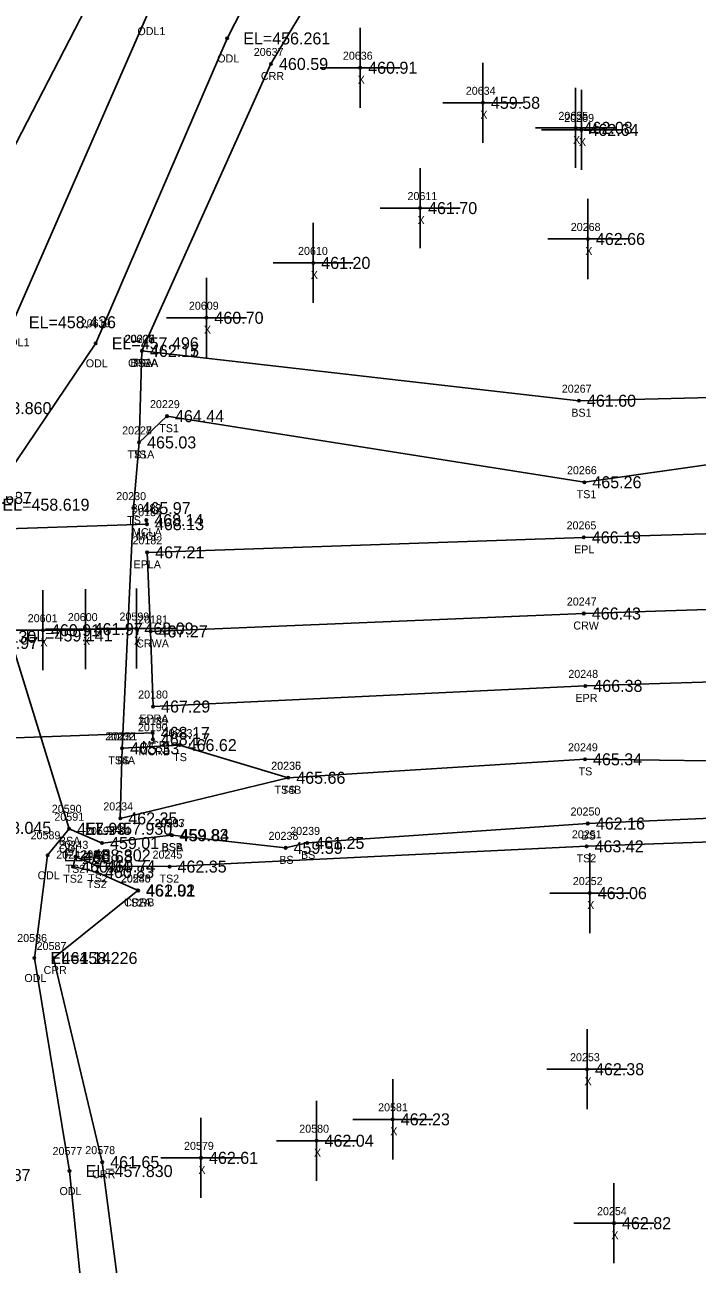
# Model space of a CAD drawing. Extents: x 1785066 to 1786589, y 770293 to 771312.
# Drawn here: x 1785809.3 to 1785893.3, y 770775.9 to 770930.8 of the extents above; entities that cross this region are included whole.
import ezdxf

# ---------------------------------------------------------------- set-up
doc = ezdxf.new("R2010")
doc.units = 0
for name, color, linetype in [('BR_500YR_SCOUR', 7, 'Continuous'), ('RD_DTM_BkLn1', 7, 'Continuous'), ('RD_DTM_BkLn2', 7, 'Continuous'), ('RD_DTM_BkLn_txCode', 7, 'Continuous'), ('RD_EX_Conc_txCode', 7, 'Continuous'), ('RD_EX_H2O', 7, 'Continuous'), ('RD_EX_H2O_txCode', 7, 'Continuous'), ('RD_EX_Misc', 7, 'Continuous'), ('RD_EX_Misc_txCode', 7, 'Continuous'), ('RD_EX_Road', 7, 'Continuous'), ('RD_EX_Road_txCode', 7, 'Continuous'), ('RD_EX_TX_Conc_ELEV', 7, 'Continuous'), ('RD_EX_TX_H2O_ELEV', 7, 'Continuous'), ('RD_EX_TX_Misc_ELEV', 7, 'Continuous'), ('RD_EX_TX_Road_ELEV', 7, 'Continuous'), ('RD_HC_Survey_ELEV', 7, 'Continuous'), ('RD_HC_Survey_txCode', 7, 'Continuous'), ('RD_SMD_Locator', 7, 'Continuous')]:
    doc.layers.add(name, color=color, linetype=linetype)

msp = doc.modelspace()

# ---------------------------------------------------------------- linework, layer by layer
at = {"layer": 'BR_500YR_SCOUR'}
for points in [[(1785824.45, 770868.88), (1785824.54, 770868.38), (1785779.78, 770866.9), (1785779.66, 770867.5)], [(1785780.7, 770840.08), (1785780.59, 770840.7), (1785825.26, 770842.31), (1785825.28, 770841.51)]]:
    msp.add_lwpolyline(points, dxfattribs=at)
for centre in [(1785824.45, 770868.88), (1785824.54, 770868.38), (1785825.26, 770842.31), (1785825.28, 770841.51)]:
    msp.add_circle(centre, 0.15, dxfattribs=at)
at = {"layer": 'RD_DTM_BkLn1'}
msp.add_lwpolyline([(1785825, 770854.98), (1785879.1, 770857.22), (1785979.05, 770860.47), (1786078.95, 770863.87), (1786178.85, 770867.23), (1786278.74, 770870.52), (1786378.69, 770873.93), (1786478.55, 770877.83), (1786578.48, 770880.72)], dxfattribs=at)
at = {"layer": 'RD_DTM_BkLn2'}
for points in [[(1785823.92, 770890.03), (1785878.49, 770883.8), (1785927.98, 770885.02), (1785976.75, 770881.71), (1786078.01, 770885.31), (1786179.02, 770889.42), (1786277.82, 770892.61), (1786356.85, 770898.28)], [(1785823.56, 770878.59), (1785827.04, 770881.87), (1785879.17, 770873.62), (1785928.77, 770880.68), (1785976.07, 770878.36), (1786078.31, 770882.72), (1786179.21, 770888.23), (1786278, 770891.06), (1786358.22, 770894.11)], [(1785823.92, 770890.03), (1785823.56, 770878.59), (1785822.86, 770870.38), (1785821.44, 770840.38), (1785828.62, 770840.78), (1785842.19, 770836.7), (1785879.25, 770839.01), (1785978.35, 770837.69), (1786078.6, 770842.58), (1786178.83, 770845.52), (1786229.23, 770850.73), (1786230.88, 770847.03), (1786230.86, 770843.81)], [(1785827.67, 770829.52), (1785841.85, 770827.95), (1785844.56, 770828.57), (1785879.6, 770830.99), (1785978.6, 770835.28), (1786078.94, 770840.43), (1786179.05, 770843.41), (1786228.83, 770846.64)], [(1785823.45, 770822.61), (1785818.3, 770824.93), (1785815.32, 770825.6), (1785815.62, 770826.83), (1785818.45, 770825.65), (1785827.36, 770825.61), (1785879.44, 770828.14), (1785979.38, 770831.62), (1786079.14, 770836.17), (1786182.02, 770840.89), (1786230.86, 770843.81)], [(1785821.44, 770840.38), (1785821.21, 770831.63), (1785842.19, 770836.7)], [(1785814.82, 770830.33), (1785818.93, 770828.55), (1785827.6, 770829.55)]]:
    msp.add_lwpolyline(points, dxfattribs=at)
at = {"layer": 'RD_EX_H2O'}
for points in [[(1785796.94, 770894.21), (1785817.52, 770934.08), (1785841.28, 770978.27), (1785905.84, 771069.13), (1785934.06, 771107.4), (1785932.74, 771138.87), (1785957.1, 771183.16), (1785993.97, 771208.54), (1785990.48, 771236.16), (1786004.55, 771296.27)], [(1785809.1, 770721.92), (1785797.13, 770787.08), (1785799.71, 770830.45), (1785797.84, 770854.32), (1785797.31, 770871.66), (1785799.74, 770882.87), (1785807.79, 770893.6), (1785824.76, 770932.46), (1785830, 770936.66), (1785845.12, 770978.01), (1785907.84, 771068.37), (1785939.25, 771107.77), (1785943.33, 771137.21), (1785960.57, 771178.58), (1785995.85, 771206.75), (1786007.06, 771230.75), (1786010.67, 771288.67)], [(1785820.66, 770730.64), (1785814.87, 770787.58), (1785810.48, 770814.19), (1785812.13, 770827.02), (1785814.82, 770830.33), (1785807.38, 770854.48), (1785804.49, 770870.81), (1785818.14, 770890.97), (1785834.56, 770929.05), (1785857.87, 770974.7), (1785917.08, 771062.46), (1785943.86, 771096.04), (1785952.84, 771134.11), (1785966.16, 771175.54), (1786004.33, 771202.23), (1786012.95, 771230.11), (1786017.56, 771287.45)], [(1785823.91, 770890.02), (1785840.03, 770925.86), (1785869.79, 770975.48), (1785920.39, 771060.62), (1785947.12, 771092.26), (1785958.51, 771131.14), (1785974.06, 771169.93), (1786009.64, 771197.71), (1786027.99, 771233.04), (1786021.73, 771286.51)], [(1785996.34, 770328.69), (1785988.37, 770343.77), (1785978.71, 770369.85), (1785965.55, 770429.48), (1785948.02, 770485.76), (1785915.42, 770547.17), (1785885.85, 770601.99), (1785867.88, 770639.76), (1785836.38, 770688.5), (1785826.2, 770733.3), (1785818.95, 770788.69), (1785812.88, 770814.19), (1785823.4, 770822.64)]]:
    msp.add_lwpolyline(points, dxfattribs=at)
at = {"layer": 'RD_EX_Misc'}
for p, q in [((1785851.17, 770920.39), (1785851.17, 770930.39)), ((1785846.17, 770925.39), (1785856.17, 770925.39)), ((1785866.5, 770916.01), (1785866.5, 770926.01)), ((1785878.07, 770912.88), (1785878.07, 770922.88)), ((1785878.8, 770912.62), (1785878.8, 770922.62)), ((1785861.5, 770921.01), (1785871.5, 770921.01)), ((1785873.07, 770917.88), (1785883.07, 770917.88)), ((1785873.8, 770917.62), (1785883.8, 770917.62)), ((1785858.65, 770902.86), (1785858.65, 770912.86)), ((1785853.65, 770907.86), (1785863.65, 770907.86)), ((1785879.61, 770899), (1785879.61, 770909)), ((1785845.31, 770896.01), (1785845.31, 770906.01)), ((1785874.61, 770904), (1785884.61, 770904)), ((1785840.31, 770901.01), (1785850.31, 770901.01)), ((1785831.97, 770889.16), (1785831.97, 770899.16)), ((1785826.97, 770894.16), (1785836.97, 770894.16)), ((1785811.55, 770850.13), (1785811.55, 770860.13)), ((1785816.88, 770850.27), (1785816.88, 770860.27)), ((1785823.23, 770850.34), (1785823.23, 770860.34)), ((1785806.55, 770855.13), (1785816.55, 770855.13)), ((1785811.88, 770855.27), (1785821.88, 770855.27)), ((1785818.23, 770855.34), (1785828.23, 770855.34)), ((1785879.84, 770817.3), (1785879.84, 770827.3)), ((1785874.84, 770822.3), (1785884.84, 770822.3)), ((1785879.5, 770795.3), (1785879.5, 770805.3)), ((1785874.5, 770800.3), (1785884.5, 770800.3)), ((1785855.24, 770789.04), (1785855.24, 770799.04)), ((1785845.72, 770786.37), (1785845.72, 770796.37)), ((1785831.29, 770784.23), (1785831.29, 770794.23)), ((1785850.24, 770794.04), (1785860.24, 770794.04)), ((1785840.72, 770791.37), (1785850.72, 770791.37)), ((1785826.29, 770789.23), (1785836.29, 770789.23)), ((1785882.87, 770776.07), (1785882.87, 770786.07)), ((1785877.87, 770781.07), (1785887.87, 770781.07))]:
    msp.add_line(p, q, dxfattribs=at)
at = {"layer": 'RD_EX_Road'}
for points in [[(1785824.57, 770864.86), (1785879.1, 770866.73), (1785977.08, 770869.67), (1786078.78, 770873.52), (1786179.09, 770876.83), (1786278.08, 770880.28), (1786358.72, 770883.31), (1786381.38, 770883.94), (1786478.25, 770886.75), (1786578.04, 770889.63)], [(1785825.31, 770845.6), (1785879.29, 770848.18), (1785979.17, 770851.29), (1786079.29, 770854.66), (1786178.79, 770858.1), (1786233.56, 770860.16), (1786246.2, 770860.52), (1786278.61, 770861.3), (1786379.15, 770864.94), (1786479.01, 770868.57), (1786578.78, 770871.53)], [(1785825.31, 770845.6), (1785825, 770854.98), (1785824.57, 770864.86)]]:
    msp.add_lwpolyline(points, dxfattribs=at)
at = {"layer": 'RD_SMD_Locator'}
for centre in [(1785834.56, 770929.05), (1785840.03, 770925.86), (1785851.17, 770925.39), (1785866.5, 770921.01), (1785878.07, 770917.88), (1785878.8, 770917.62), (1785858.65, 770907.86), (1785879.61, 770904), (1785845.31, 770901.01), (1785831.97, 770894.16), (1785818.14, 770890.97), (1785823.91, 770890.02), (1785823.92, 770890.03), (1785823.92, 770890.03), (1785878.49, 770883.8), (1785827.04, 770881.87), (1785823.56, 770878.59), (1785823.56, 770878.59), (1785879.17, 770873.62), (1785822.86, 770870.38), (1785879.1, 770866.73), (1785824.57, 770864.86), (1785879.1, 770857.22), (1785811.55, 770855.13), (1785816.88, 770855.27), (1785823.23, 770855.34), (1785825, 770854.98), (1785879.29, 770848.18), (1785825.31, 770845.6), (1785821.44, 770840.38), (1785821.44, 770840.38), (1785828.62, 770840.78), (1785879.25, 770839.01), (1785842.19, 770836.7), (1785842.19, 770836.7), (1785814.82, 770830.33), (1785814.82, 770830.33), (1785821.21, 770831.63), (1785879.6, 770830.99), (1785827.6, 770829.55), (1785827.67, 770829.52), (1785844.56, 770828.57), (1785812.13, 770827.02), (1785818.93, 770828.55), (1785841.85, 770827.95), (1785879.44, 770828.14), (1785815.32, 770825.6), (1785815.62, 770826.83), (1785818.45, 770825.65), (1785827.36, 770825.61), (1785818.3, 770824.93), (1785823.4, 770822.64), (1785823.45, 770822.61), (1785879.84, 770822.3), (1785810.48, 770814.19), (1785812.88, 770814.19), (1785879.5, 770800.3), (1785855.24, 770794.04), (1785845.72, 770791.37), (1785818.95, 770788.69), (1785831.29, 770789.23), (1785814.87, 770787.58), (1785882.87, 770781.07)]:
    msp.add_circle(centre, 0.15, dxfattribs=at)

# ---------------------------------------------------------------- texts
at = {"layer": 'RD_DTM_BkLn_txCode'}
for s, p in [('20226', (1785821.78, 770891.03)), ('20225', (1785821.8, 770891.03)), ('BS1A', (1785822.49, 770888.03)), ('TSA', (1785822.64, 770888.03)), ('20267', (1785876.35, 770884.8)), ('20229', (1785824.92, 770882.87)), ('BS1', (1785877.54, 770881.8)), ('20227', (1785821.44, 770879.59)), ('20228', (1785821.44, 770879.59)), ('TS1', (1785826.08, 770879.87)), ('TS1A', (1785822.11, 770876.59)), ('TS', (1785822.77, 770876.59)), ('20266', (1785877, 770874.62)), ('20230', (1785820.71, 770871.38)), ('TS1', (1785878.21, 770871.62)), ('TS', (1785822.07, 770868.38)), ('20233', (1785826.5, 770841.78)), ('20232', (1785819.32, 770841.38)), ('20231', (1785819.61, 770841.38)), ('TS', (1785827.82, 770838.78)), ('20249', (1785877.13, 770840.01)), ('TS4A', (1785819.71, 770838.38)), ('TS', (1785820.64, 770838.38)), ('20236', (1785840.05, 770837.7)), ('20235', (1785840.07, 770837.7)), ('TS', (1785878.45, 770837.01)), ('TS4B', (1785840.47, 770834.7)), ('TS', (1785841.39, 770834.7)), ('20234', (1785819.09, 770832.63)), ('20591', (1785812.98, 770831.33)), ('20250', (1785877.45, 770831.99)), ('20592', (1785816.81, 770829.55)), ('TS4', (1785819.97, 770829.63)), ('20593', (1785825.49, 770830.55)), ('20237', (1785825.55, 770830.52)), ('20239', (1785842.44, 770829.57)), ('20243', (1785813.5, 770827.83)), ('BSA', (1785813.55, 770828.33)), ('20238', (1785839.73, 770828.95)), ('20251', (1785877.61, 770829.14)), ('BS', (1785878.82, 770828.99)), ('20242', (1785813.21, 770826.6)), ('20244', (1785816.33, 770826.65)), ('BS', (1785818.15, 770826.55)), ('20245', (1785825.24, 770826.61)), ('BSB', (1785826.35, 770827.55)), ('BSA', (1785826.4, 770827.52)), ('BS', (1785843.78, 770826.57)), ('TS2', (1785878.2, 770826.14)), ('TS2', (1785814.38, 770824.83)), ('20241', (1785816.46, 770825.93)), ('BS', (1785841.07, 770825.95)), ('TS2', (1785814.08, 770823.6)), ('TS2', (1785817.2, 770823.65)), ('20240', (1785821.29, 770823.61)), ('TS2', (1785826.11, 770823.61)), ('TS2', (1785817.05, 770822.93)), ('TS2A', (1785821.72, 770820.61))]:
    msp.add_text(s, height=1, dxfattribs=at).set_placement(p)
at = {"layer": 'RD_EX_Conc_txCode'}
for s, p in [('20183', (1785822.62, 770869.88)), ('20184', (1785822.7, 770869.38)), ('MCLA', (1785822.67, 770866.88)), ('MCL', (1785823.24, 770866.38)), ('20189', (1785823.43, 770843.31)), ('20190', (1785823.41, 770842.51)), ('MCR', (1785823.95, 770840.31)), ('MCRB', (1785823.5, 770839.51))]:
    msp.add_text(s, height=1, dxfattribs=at).set_placement(p)
at = {"layer": 'RD_EX_H2O_txCode'}
for s, p in [('ODL1', (1785823.35, 770929.46)), ('20637', (1785837.88, 770926.86)), ('ODL', (1785833.32, 770926.05)), ('CRR', (1785838.77, 770923.86)), ('20619', (1785816.28, 770892.97)), ('ODL1', (1785806.38, 770890.6)), ('20608', (1785821.73, 770891.02)), ('ODL', (1785816.9, 770887.97)), ('CRRA', (1785822.17, 770888.02)), ('20590', (1785812.66, 770832.33)), ('20589', (1785810.01, 770829.02)), ('ODL', (1785813.57, 770827.33)), ('ODL', (1785810.89, 770824.02)), ('20588', (1785821.28, 770823.64)), ('CRRB', (1785821.68, 770820.64)), ('20586', (1785808.34, 770816.19)), ('20587', (1785810.76, 770815.19)), ('ODL', (1785809.23, 770811.19)), ('CRR', (1785811.63, 770812.19)), ('20577', (1785812.75, 770789.58)), ('20578', (1785816.84, 770789.69)), ('CRR', (1785817.7, 770786.69)), ('ODL', (1785813.62, 770784.58))]:
    msp.add_text(s, height=1, dxfattribs=at).set_placement(p)
at = {"layer": 'RD_EX_Misc_txCode'}
for s, p in [('20636', (1785849.01, 770926.39)), ('X', (1785850.86, 770923.39)), ('20634', (1785864.36, 770922.01)), ('X', (1785866.18, 770919.01)), ('20635', (1785875.93, 770918.88)), ('20269', (1785876.66, 770918.62)), ('X', (1785877.76, 770915.88)), ('X', (1785878.49, 770915.62)), ('20611', (1785857.08, 770908.86)), ('X', (1785858.34, 770905.86)), ('20268', (1785877.47, 770905)), ('20610', (1785843.41, 770902.01)), ('X', (1785879.29, 770902)), ('X', (1785845, 770899.01)), ('20609', (1785829.78, 770895.16)), ('X', (1785831.65, 770892.16)), ('20601', (1785809.65, 770856.13)), ('20600', (1785814.66, 770856.27)), ('20599', (1785821.11, 770856.34)), ('X', (1785811.23, 770853.13)), ('X', (1785816.57, 770853.27)), ('X', (1785822.92, 770853.34)), ('20252', (1785877.73, 770823.3)), ('X', (1785879.53, 770820.3)), ('20253', (1785877.38, 770801.3)), ('X', (1785879.19, 770798.3)), ('20581', (1785853.41, 770795.04)), ('20580', (1785843.56, 770792.37)), ('X', (1785854.93, 770792.04)), ('20579', (1785829.17, 770790.23)), ('X', (1785845.4, 770789.37)), ('X', (1785830.97, 770787.23)), ('20254', (1785880.75, 770782.07)), ('X', (1785882.55, 770779.07))]:
    msp.add_text(s, height=1, dxfattribs=at).set_placement(p)
at = {"layer": 'RD_EX_Road_txCode'}
for s, p in [('20265', (1785876.95, 770867.73)), ('20182', (1785822.73, 770865.86)), ('EPL', (1785877.89, 770864.73)), ('EPLA', (1785822.87, 770862.86)), ('20248', (1785877.17, 770849.18)), ('20180', (1785823.44, 770846.6)), ('EPR', (1785878.06, 770846.18)), ('EPRA', (1785823.59, 770843.6))]:
    msp.add_text(s, height=1, dxfattribs=at).set_placement(p)
at = {"layer": 'RD_EX_TX_Conc_ELEV'}
for s, p in [('468.14', (1785825.45, 770868.13)), ('468.13', (1785825.54, 770867.63)), ('468.17', (1785826.26, 770841.56)), ('468.17', (1785826.28, 770840.76))]:
    msp.add_text(s, height=1.5, dxfattribs=at).set_placement(p)
at = {"layer": 'RD_EX_TX_H2O_ELEV'}
for s, p in [('EL=456.261', (1785836.56, 770928.3)), ('460.59', (1785841.03, 770925.11)), ('EL=458.436', (1785809.79, 770892.85)), ('EL=457.496', (1785820.14, 770890.22)), ('462.15', (1785824.91, 770889.27)), ('EL=458.860', (1785801.74, 770882.12)), ('EL=458.687', (1785799.31, 770870.91)), ('EL=458.619', (1785806.49, 770870.06)), ('EL=459.130', (1785799.84, 770853.57)), ('EL=459.141', (1785809.38, 770853.73)), ('EL=458.045', (1785801.71, 770829.7)), ('EL=457.930', (1785816.82, 770829.58)), ('EL=458.302', (1785814.13, 770826.27)), ('461.92', (1785824.4, 770821.89)), ('EL=458.226', (1785812.48, 770813.44)), ('461.14', (1785813.88, 770813.44)), ('461.65', (1785819.95, 770787.94)), ('EL=458.087', (1785799.13, 770786.33)), ('EL=457.830', (1785816.87, 770786.83))]:
    msp.add_text(s, height=1.5, dxfattribs=at).set_placement(p)
at = {"layer": 'RD_EX_TX_Misc_ELEV'}
for s, p in [('460.91', (1785852.17, 770924.64)), ('459.58', (1785867.5, 770920.26)), ('462.08', (1785879.07, 770917.13)), ('462.64', (1785879.8, 770916.87)), ('461.70', (1785859.65, 770907.11)), ('462.66', (1785880.61, 770903.25)), ('461.20', (1785846.31, 770900.26)), ('460.70', (1785832.97, 770893.41)), ('462.17', (1785824.92, 770889.28)), ('462.17', (1785824.92, 770889.28)), ('461.60', (1785879.49, 770883.05)), ('464.44', (1785828.04, 770881.12)), ('465.03', (1785824.56, 770877.84)), ('465.03', (1785824.56, 770877.84)), ('465.26', (1785880.17, 770872.87)), ('465.97', (1785823.86, 770869.63)), ('460.91', (1785812.55, 770854.38)), ('461.97', (1785817.88, 770854.52)), ('463.09', (1785824.23, 770854.59)), ('458.97', (1785804.81, 770852.8)), ('465.33', (1785822.44, 770839.63)), ('465.33', (1785822.44, 770839.63)), ('466.62', (1785829.62, 770840.03)), ('465.34', (1785880.25, 770838.26)), ('465.66', (1785843.19, 770835.95)), ('465.66', (1785843.19, 770835.95)), ('462.35', (1785822.21, 770830.88)), ('457.93', (1785815.82, 770829.58)), ('459.83', (1785828.6, 770828.8)), ('459.84', (1785828.67, 770828.77)), ('462.16', (1785880.6, 770830.24)), ('459.01', (1785819.93, 770827.8)), ('459.59', (1785842.85, 770827.2)), ('461.25', (1785845.56, 770827.82)), ('463.42', (1785880.44, 770827.39)), ('460.68', (1785816.62, 770826.08)), ('460.84', (1785816.32, 770824.85)), ('460.83', (1785819.3, 770824.18)), ('460.74', (1785819.45, 770824.9)), ('462.35', (1785828.36, 770824.86)), ('462.01', (1785824.45, 770821.86)), ('463.06', (1785880.84, 770821.55)), ('462.38', (1785880.5, 770799.55)), ('462.23', (1785856.24, 770793.29)), ('462.04', (1785846.72, 770790.62)), ('462.61', (1785832.29, 770788.48)), ('462.82', (1785883.87, 770780.32))]:
    msp.add_text(s, height=1.5, dxfattribs=at).set_placement(p)
at = {"layer": 'RD_EX_TX_Road_ELEV'}
for s, p in [('466.19', (1785880.1, 770865.98)), ('467.21', (1785825.57, 770864.11)), ('466.38', (1785880.29, 770847.43)), ('467.29', (1785826.31, 770844.85))]:
    msp.add_text(s, height=1.5, dxfattribs=at).set_placement(p)
at = {"layer": 'RD_HC_Survey_ELEV'}
for s, p in [('466.43', (1785880.1, 770856.47)), ('467.27', (1785826, 770854.23))]:
    msp.add_text(s, height=1.5, dxfattribs=at).set_placement(p)
at = {"layer": 'RD_HC_Survey_txCode'}
for s, p in [('20247', (1785876.98, 770858.22)), ('20181', (1785823.45, 770855.98)), ('CRW', (1785877.79, 770855.22)), ('CRWA', (1785823.2, 770852.98))]:
    msp.add_text(s, height=1, dxfattribs=at).set_placement(p)

doc.saveas('drawing.dxf')
